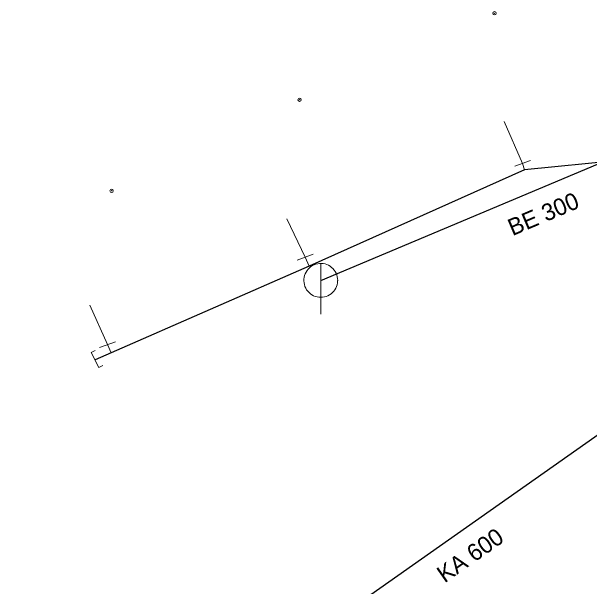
# Model space of a CAD drawing. Extents: x -783064 to -782702, y -1007904 to -1007145.
# Drawn here: x -782871.02 to -782836.85, y -1007741.38 to -1007707.42 of the extents above; entities that cross this region are included whole.
import ezdxf

# ---------------------------------------------------------------- set-up
doc = ezdxf.new("R2010")
doc.units = 0
doc.header["$LTSCALE"] = 0.4
doc.header["$PDMODE"] = 32
doc.header["$PDSIZE"] = 0.2
for name, color, linetype, lineweight in [('1', 7, 'Continuous', 13), ('13', 7, 'Continuous', 13), ('14', 7, 'Continuous', 13), ('17', 7, 'Continuous', 25), ('22', 7, 'Continuous', 13), ('34', 7, 'Continuous', 13), ('47', 7, 'Continuous', 13)]:
    doc.layers.add(name, color=color, linetype=linetype, lineweight=lineweight)

msp = doc.modelspace()

# ---------------------------------------------------------------- linework, layer by layer
at = {"layer": '1'}
for p in [(-782842.469, -1007707.519), (-782853.989, -1007712.629), (-782865.109, -1007718.009)]:
    msp.add_point(p, dxfattribs=at)
at = {"layer": '13'}
for p, q in [((-782840.804, -1007716.39), (-782841.9, -1007713.908)), ((-782853.669, -1007721.931), (-782854.749, -1007719.666)), ((-782865.345, -1007727.096), (-782866.402, -1007724.767))]:
    msp.add_line(p, q, dxfattribs=at)
at = {"layer": '14', "lineweight": 25}
for p, q in [((-782852.739, -1007723.3), (-782826.079, -1007712.1)), ((-782871.02, -1007756.76), (-782817.19, -1007718.96))]:
    msp.add_line(p, q, dxfattribs=at)
at = {"layer": '14'}
for p, q in [((-782840.693, -1007716.775), (-782840.804, -1007716.39)), ((-782853.429, -1007722.469), (-782853.669, -1007721.931)), ((-782865.128, -1007727.585), (-782865.345, -1007727.096))]:
    msp.add_line(p, q, dxfattribs=at)
at = {"layer": '17'}
msp.add_lwpolyline([(-782818.39, -1007714.56), (-782840.693, -1007716.775), (-782853.429, -1007722.469), (-782865.128, -1007727.585), (-782866.08, -1007728.001)], dxfattribs=at)
at = {"layer": '22'}
msp.add_line((-782852.739, -1007725.3), (-782852.738, -1007722.3), dxfattribs=at)
msp.add_lwpolyline([(-782851.739, -1007723.3), (-782851.744, -1007723.191), (-782851.762, -1007723.083), (-782851.792, -1007722.977), (-782851.832, -1007722.876), (-782851.884, -1007722.779), (-782851.946, -1007722.689), (-782852.018, -1007722.606), (-782852.098, -1007722.532), (-782852.186, -1007722.466), (-782852.28, -1007722.411), (-782852.38, -1007722.366), (-782852.485, -1007722.333), (-782852.592, -1007722.311), (-782852.701, -1007722.301), (-782852.811, -1007722.303), (-782852.919, -1007722.317), (-782853.026, -1007722.342), (-782853.129, -1007722.379), (-782853.227, -1007722.428), (-782853.319, -1007722.486), (-782853.405, -1007722.555), (-782853.482, -1007722.632), (-782853.551, -1007722.718), (-782853.61, -1007722.81), (-782853.658, -1007722.908), (-782853.695, -1007723.011), (-782853.721, -1007723.118), (-782853.735, -1007723.226), (-782853.738, -1007723.336), (-782853.728, -1007723.445), (-782853.707, -1007723.552), (-782853.673, -1007723.656), (-782853.629, -1007723.756), (-782853.574, -1007723.851), (-782853.508, -1007723.939), (-782853.434, -1007724.019), (-782853.351, -1007724.091), (-782853.261, -1007724.153), (-782853.165, -1007724.205), (-782853.063, -1007724.246), (-782852.958, -1007724.276), (-782852.85, -1007724.294), (-782852.74, -1007724.3), (-782852.631, -1007724.294), (-782852.523, -1007724.276), (-782852.418, -1007724.247), (-782852.316, -1007724.206), (-782852.219, -1007724.154), (-782852.129, -1007724.092), (-782852.046, -1007724.021), (-782851.971, -1007723.941), (-782851.906, -1007723.853), (-782851.85, -1007723.759), (-782851.806, -1007723.659), (-782851.772, -1007723.555), (-782851.75, -1007723.447), (-782851.74, -1007723.338)], close=True, dxfattribs=at)
at = {"layer": '34'}
for p, q in [((-782840.333, -1007716.22), (-782841.274, -1007716.558)), ((-782853.198, -1007721.761), (-782854.139, -1007722.099)), ((-782864.874, -1007726.926), (-782865.815, -1007727.264))]:
    msp.add_line(p, q, dxfattribs=at)
at = {"layer": '47'}
msp.add_lwpolyline([(-782865.63, -1007728.328), (-782865.854, -1007728.442), (-782866.305, -1007727.559), (-782866.08, -1007727.444)], dxfattribs=at)

# ---------------------------------------------------------------- texts
at = {"layer": '1'}
for s, rotation, p in [('BE 300', 23, (-782841.406, -1007720.691)), ('KA 600', 35, (-782845.418, -1007741.208))]:
    msp.add_text(s, height=1, rotation=rotation, dxfattribs=at).set_placement(p)

doc.saveas('drawing.dxf')
